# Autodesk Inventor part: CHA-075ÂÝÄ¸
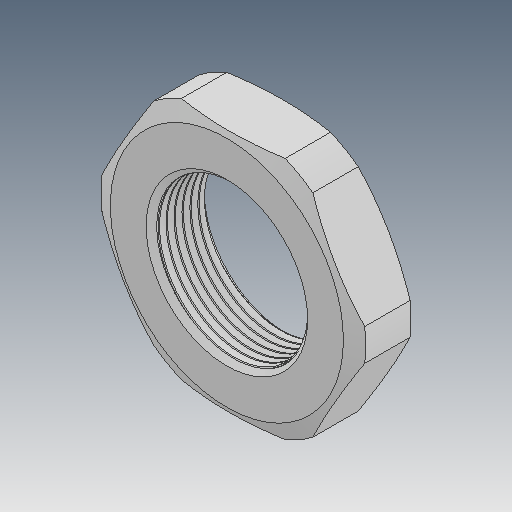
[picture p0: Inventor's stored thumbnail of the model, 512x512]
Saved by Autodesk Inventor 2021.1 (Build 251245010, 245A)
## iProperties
Created: 2019-05
Part Number: CHA-075ÂÝÄ¸
Material: Ogólny
Document SubType Name: Modeling
Designer: user
Density: 1 g/cm^3
Appearance: Domyślna
Author: user
Revision Number: ÈÎºÎ
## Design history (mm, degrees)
feature "¾µÏò1"
node "Bryła1"
